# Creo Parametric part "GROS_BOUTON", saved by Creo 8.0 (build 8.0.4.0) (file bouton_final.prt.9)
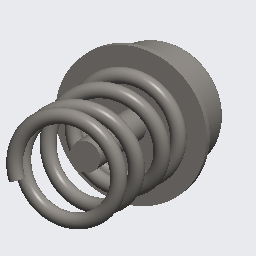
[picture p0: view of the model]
Materials in the file: FR_ACIER_E335

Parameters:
  DESIGNATION = "COMPOSANT CREO"
  PRENOM_DESSINATEUR = ")"
  MATIERE = "FR_ACIER_E335"
  DESSINATEUR = ": - )"
  PTC_MATERIAL_NAME = "FR_ACIER_E335"
  DESCRIPTION = "Concu a l'INSA de Strasbourg"
  VERSION_CREATION = "CREO 8.0"
  MATERIAL = "FR_ACIER_E335"
  DESIGNER_FIRST_NAME = ")"
  DESIGNER_NAME = ":"
  DESIGNER = ": - )"
  DESIGN_RELEASE = "CREO 8.0"
  PTC_MASTER_MATERIAL = "FR_ACIER_E335"
  NORME = "ACIER_A60"

Other parameters: MASSE, VOLUME, MASS, SURF_AREA, XCOG, YCOG, ZCOG, THERM_EXPANSION_REF_TEMPERATURE, STRESS_LIMIT_FOR_TENSION, STRESS_LIMIT_FOR_SHEAR, D21, D22

Created from: FR_MMNS_PIECE_SOLIDE.PRT

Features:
  1. datum plane "PRT_FACE"
  2. datum plane "PRT_DESSUS"
  3. datum plane "PRT_DROITE"
  4. coordinate system
  5. datum point "CDG"
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
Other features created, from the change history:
  revolve "Revolution 1"
  sketch "Esquisse 1"
  protrusion "Balayage Hélicoïdal 1"
  protrusion "Balayage Hélicoïdal 2" (2 times)
  extrusion "Extrude 1"

Other named items: PRT_REP, MASS_PROP, ZONE1-SECTION, PROP_MASSIQUES, CENTRE_GRAVITE, FACE, ARRIERE, DESSUS, DESSOUS, DROITE, GAUCHE, ANNOT_LAYER_STATE0001, ANNOT_LAYER_STATE0002, ANNOT_LAYER_STATE0003, ANNOT_LAYER_STATE0004, ANNOT_LAYER_STATE0005, ANNOT_LAYER_STATE0006

Notes: MASSE :  | 0,07 | VOLUME :  | 8,866 |  cm3 | Centre de Gravité | X :  | 0,037 | Y :  | -0,003 | Z :  | -1,672 |   mm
